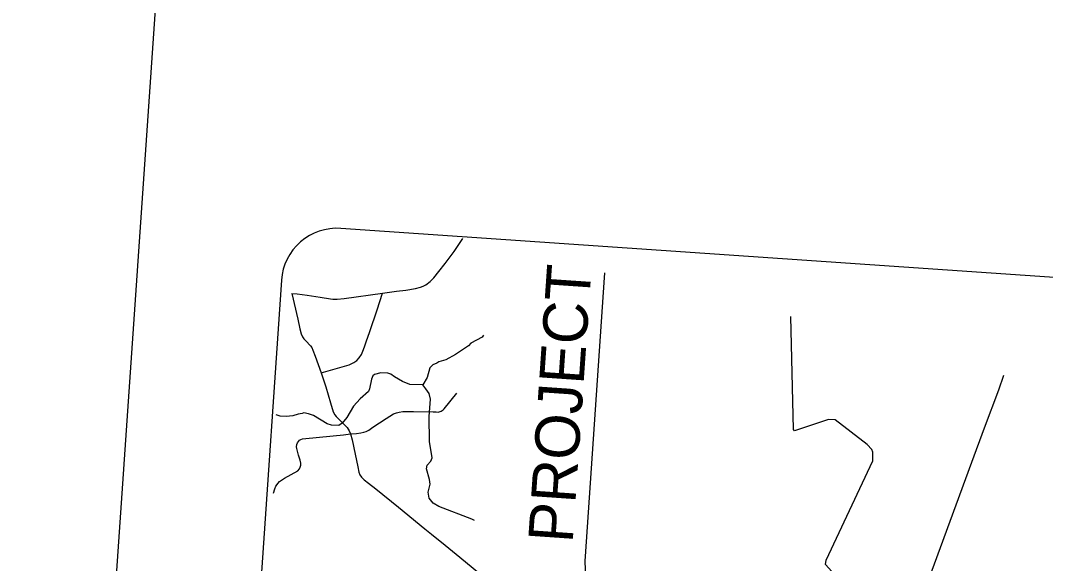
# Model space of a CAD drawing. Extents: x 2599057 to 2600057, y 728628 to 732947.
# Drawn here: x 2599056.6 to 2599259.1, y 731906.7 to 732014 of the extents above; entities that cross this region are included whole.
import ezdxf

# ---------------------------------------------------------------- set-up
doc = ezdxf.new("R2010")
doc.units = 0
for name, color, linetype in [('CTL Sheet Border CELL', 7, 'Continuous'), ('Old_Level_1', 7, 'Continuous'), ('Old_Level_32', 7, 'Continuous'), ('Old_Level_50', 7, 'Continuous'), ('Old_Level_59', 7, 'Continuous')]:
    doc.layers.add(name, color=color, linetype=linetype)

msp = doc.modelspace()

# ---------------------------------------------------------------- linework, layer by layer
at = {"layer": 'CTL Sheet Border CELL'}
msp.add_lwpolyline([(2599146.23, 732931.19), (2599056.61, 731629.92), (2599967.49, 731567.19), (2600057.11, 732868.45)], close=True, dxfattribs=at)
at = {"layer": 'Old_Level_1'}
for p, q in [((2599385.99, 731954.58), (2599119.9, 731972.9)), ((2599168.16, 731907.13), (2599172.08, 731964.11)), ((2599108.17, 731962.68), (2599087.2, 731658.27)), ((2599170.91, 731834.22), (2599168.16, 731907.13))]:
    msp.add_line(p, q, dxfattribs=at)
msp.add_arc((2599119.14, 731961.93), 11, 86.06, 176.0601, dxfattribs=at)
at = {"layer": 'Old_Level_32'}
for points in [[(2599128.1, 731960.09), (2599130.89, 731960.5), (2599132.75, 731960.7), (2599134.62, 731961.01), (2599135.66, 731961.28), (2599136.16, 731961.48), (2599136.7, 731961.75), (2599137.56, 731962.41), (2599138.3, 731963.12), (2599139.29, 731964.37), (2599140.5, 731965.97), (2599142.28, 731968.33), (2599143.97, 731970.88)], [(2599110.24, 731960.04), (2599111.25, 731959.99), (2599113.22, 731959.69), (2599115.8, 731959.3), (2599117.84, 731958.99), (2599118.29, 731958.95), (2599119.18, 731958.95), (2599120.58, 731959.07), (2599128.1, 731960.09)], [(2599110.24, 731960.04), (2599111.38, 731955), (2599111.8, 731953.07), (2599112.04, 731952.09), (2599112.3, 731951.5), (2599112.61, 731951.07), (2599113, 731950.69), (2599113.91, 731949.71), (2599114.18, 731949.34), (2599114.37, 731948.87), (2599114.82, 731947.63), (2599115.98, 731944.34)], [(2599115.98, 731944.34), (2599121.54, 731945.95), (2599122.47, 731946.4), (2599123.03, 731946.77), (2599123.53, 731947.3), (2599123.96, 731947.97), (2599124.27, 731948.62), (2599124.58, 731949.48), (2599124.89, 731950.52), (2599125.6, 731952.52), (2599127.05, 731956.79), (2599128.1, 731960.09)], [(2599115.98, 731944.34), (2599116.91, 731941.59), (2599117.87, 731938.46), (2599118.41, 731936.68), (2599118.73, 731936.06), (2599118.99, 731935.71), (2599119.54, 731935.13), (2599121.12, 731933.55), (2599121.57, 731932.87), (2599121.83, 731932.33)], [(2599218.06, 731854.89), (2599221.94, 731865.36), (2599223.46, 731869.43), (2599224.29, 731871.74), (2599226.88, 731878.72), (2599227.87, 731881.42), (2599230.41, 731888.22), (2599231.23, 731890.45), (2599232.2, 731893.12), (2599237.18, 731906.61), (2599244.57, 731926.73), (2599247.08, 731933.51), (2599249.88, 731941.02), (2599250.89, 731943.93)], [(2599121.83, 731932.33), (2599122.96, 731932.4), (2599123.87, 731932.52), (2599124.41, 731932.61), (2599124.87, 731932.74), (2599125.4, 731933.03), (2599126.25, 731933.61), (2599128.86, 731935.35), (2599130.28, 731936.23), (2599130.9, 731936.47), (2599131.39, 731936.59), (2599132.14, 731936.69), (2599133.08, 731936.7), (2599134.26, 731936.74), (2599138.15, 731936.66), (2599138.75, 731936.62), (2599139.13, 731936.6), (2599139.33, 731936.66), (2599139.74, 731936.8), (2599139.89, 731936.89), (2599140.11, 731937.06), (2599140.31, 731937.25), (2599142.81, 731940.37)], [(2599106.62, 731920.59), (2599106.85, 731921.43), (2599107.08, 731921.95), (2599107.3, 731922.26), (2599107.46, 731922.51), (2599107.76, 731922.87), (2599108.77, 731923.53), (2599111.41, 731925.01), (2599111.7, 731925.36), (2599111.89, 731925.72), (2599112, 731926.13), (2599111.99, 731926.48), (2599111.85, 731927.12), (2599111.56, 731928.12), (2599111.18, 731929.42), (2599111.13, 731929.74), (2599111.22, 731930.2), (2599111.33, 731930.53), (2599111.53, 731930.81), (2599111.74, 731931.02), (2599112.02, 731931.18), (2599112.31, 731931.31), (2599115.7, 731931.64), (2599120.42, 731932.12), (2599121.83, 731932.33)], [(2599121.83, 731932.33), (2599122.15, 731931.15), (2599122.73, 731928.31), (2599123.24, 731925.8), (2599123.46, 731924.73), (2599123.68, 731924.23), (2599124.01, 731923.72), (2599124.52, 731923.23), (2599125.38, 731922.58), (2599126.78, 731921.45), (2599131.26, 731917.79), (2599136.52, 731913.52), (2599137.82, 731912.49), (2599140.48, 731910.3), (2599143.4, 731907.91), (2599150.19, 731902.36)]]:
    msp.add_lwpolyline(points, dxfattribs=at)
at = {"layer": 'Old_Level_50'}
msp.add_line((2599120.28, 731934.45), (2599120.28, 731934.45), dxfattribs=at)
at = {"layer": 'Old_Level_59'}
for points in [[(2599220.5, 731901.12), (2599219.93, 731901.71), (2599215.68, 731906.49), (2599215.77, 731907.32), (2599224.99, 731926.97), (2599225.02, 731928.7), (2599224.83, 731929.22), (2599223.88, 731930.21), (2599217.55, 731935.09), (2599216.24, 731935.15), (2599209.54, 731932.89), (2599209.3, 731933.18), (2599208.81, 731955.47)], [(2599148.11, 731951.81), (2599147.83, 731951.39), (2599145.58, 731950.21), (2599145.09, 731949.73), (2599142.58, 731948), (2599140.67, 731946.92), (2599139.26, 731946.54), (2599138.88, 731946.28), (2599138.07, 731945.92), (2599137.51, 731945.33), (2599136.93, 731943.46), (2599136.12, 731941.98)], [(2599136.12, 731941.98), (2599133.54, 731942.05), (2599132.07, 731942.63), (2599130.48, 731943.6), (2599129.76, 731944.13), (2599129.19, 731944.32), (2599127.81, 731944.39), (2599126.53, 731944.06), (2599126.25, 731943.79), (2599125.96, 731943.13), (2599125.59, 731941.19), (2599125.37, 731940.7), (2599123.69, 731939.21), (2599122.4, 731937.76), (2599121.08, 731935.53), (2599120.13, 731934.4), (2599119.47, 731933.93), (2599118.03, 731934), (2599117.21, 731934.26), (2599114.48, 731935.95), (2599113.53, 731936.27), (2599112.58, 731936.44), (2599112.26, 731936.33), (2599111.47, 731936.21), (2599110.4, 731935.87), (2599109.12, 731935.71), (2599107.89, 731935.82), (2599107.14, 731936.09)], [(2599146.31, 731915.16), (2599145.8, 731915.42), (2599139.29, 731917.96), (2599138.16, 731918.57), (2599137.36, 731919.56), (2599137.19, 731920.41), (2599137.14, 731920.8), (2599137.55, 731922.34), (2599137.43, 731923.3), (2599136.85, 731925.4), (2599136.93, 731926.12), (2599137.66, 731926.87), (2599137.95, 731927.58), (2599137.43, 731930.79), (2599137.35, 731935.72), (2599137.58, 731939.18), (2599137.32, 731940.25), (2599136.72, 731941.23), (2599136.12, 731941.98)]]:
    msp.add_lwpolyline(points, dxfattribs=at)

# ---------------------------------------------------------------- texts
at = {"layer": 'Old_Level_1'}
msp.add_text('PROJECT', height=8.8, rotation=86.0601, dxfattribs=at).set_placement((2599165.68, 731910.6))

doc.saveas('drawing.dxf')
